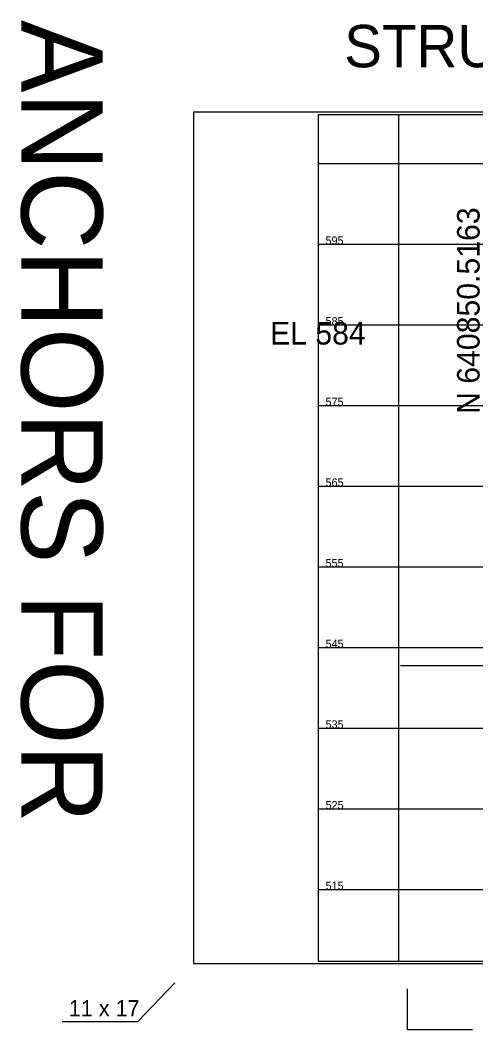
# Model space of a CAD drawing. Extents: x 278618 to 280654, y 171155 to 171855.
# Drawn here: x 279987.1 to 280043.7, y 171180.4 to 171305.6 of the extents above; entities that cross this region are included whole.
import ezdxf

# ---------------------------------------------------------------- set-up
doc = ezdxf.new("R2010")
doc.units = 0
for name, color, linetype in [('Geotech Sheets and Borders Cell', 7, 'Continuous'), ('Old_Level_39', 7, 'Continuous'), ('Prop Road Sect_ Material - Contact (General - Major)', 7, 'Continuous'), ('Prop Strc Sect_ Grid - minor', 7, 'Continuous'), ('Prop Strc Sect_ Misc - User Comment (Tx - small)', 7, 'Continuous'), ('Scratch_Level_0', 7, 'Continuous'), ('Scratch_Level_2', 7, 'Continuous'), ('Scratch_Level_4', 7, 'Continuous'), ('Sheet Plot Border Inside CELL', 7, 'Continuous')]:
    doc.layers.add(name, color=color, linetype=linetype)

msp = doc.modelspace()

# ---------------------------------------------------------------- linework, layer by layer
at = {"layer": 'Geotech Sheets and Borders Cell'}
msp.add_lwpolyline([(280024.12, 171293.86), (280174.12, 171293.86), (280174.12, 171188.86), (280024.12, 171188.86)], close=True, dxfattribs=at)
at = {"layer": 'Prop Road Sect_ Material - Contact (General - Major)'}
msp.add_line((280079.43, 171225.51), (280034.31, 171225.51), dxfattribs=at)
at = {"layer": 'Prop Strc Sect_ Grid - minor'}
for p, q in [((280034.12, 171188.86), (280034.12, 171293.86)), ((280121.53, 171287.74), (280024.12, 171287.74)), ((280174.12, 171277.74), (280024.12, 171277.74)), ((280174.12, 171267.74), (280024.12, 171267.74)), ((280174.12, 171257.74), (280024.12, 171257.74)), ((280174.12, 171247.74), (280024.12, 171247.74)), ((280174.12, 171237.74), (280024.12, 171237.74)), ((280174.12, 171227.74), (280024.12, 171227.74)), ((280174.12, 171217.74), (280024.12, 171217.74)), ((280174.12, 171207.74), (280024.12, 171207.74)), ((280174.12, 171197.74), (280024.12, 171197.74))]:
    msp.add_line(p, q, dxfattribs=at)
at = {"layer": 'Scratch_Level_0'}
msp.add_line((280008.61, 171188.58), (280008.61, 171188.58), dxfattribs=at)
msp.add_lwpolyline([(279992.34, 171181.38), (280001.73, 171181.38), (280006.32, 171186.18)], dxfattribs=at)
at = {"layer": 'Scratch_Level_4'}
msp.add_lwpolyline([(280043.22, 171180.37), (280035.19, 171180.37), (280035.19, 171185.45)], dxfattribs=at)
at = {"layer": 'Sheet Plot Border Inside CELL'}
msp.add_lwpolyline([(280008.61, 171188.58), (280175.37, 171188.58), (280175.37, 171294.14), (280008.61, 171294.14)], close=True, dxfattribs=at)

# ---------------------------------------------------------------- texts
at = {"layer": 'Geotech Sheets and Borders Cell'}
for s, p in [('595', (280025.01, 171277.74)), ('585', (280025.01, 171267.74)), ('575', (280025.01, 171257.74)), ('565', (280025.01, 171247.74)), ('555', (280025.01, 171237.74)), ('545', (280025.01, 171227.74)), ('535', (280025.01, 171217.74)), ('525', (280025.01, 171207.74)), ('515', (280025.01, 171197.74))]:
    msp.add_text(s, height=1.001, dxfattribs=at).set_placement(p)
at = {"layer": 'Old_Level_39'}
msp.add_text('N 640850.5163', height=2.8, rotation=90, dxfattribs=at).set_placement((280044.12, 171256.74))
msp.add_text('EL 584', height=2.8, dxfattribs=at).set_placement((280018.12, 171265.34))
at = {"layer": 'Prop Strc Sect_ Misc - User Comment (Tx - small)'}
msp.add_text('ANCHORS FOR', height=10.0769, rotation=270, dxfattribs=at).set_placement((279987.27, 171305.58))
at = {"layer": 'Scratch_Level_0'}
msp.add_text('11 x 17', height=2, dxfattribs=at).set_placement((279993.16, 171182.05))
at = {"layer": 'Scratch_Level_2'}
msp.add_text('STRUCTURE PROFILE SHEET, ENGLISH', height=5.25, dxfattribs=at).set_placement((280027.32, 171299.72))

doc.saveas('drawing.dxf')
